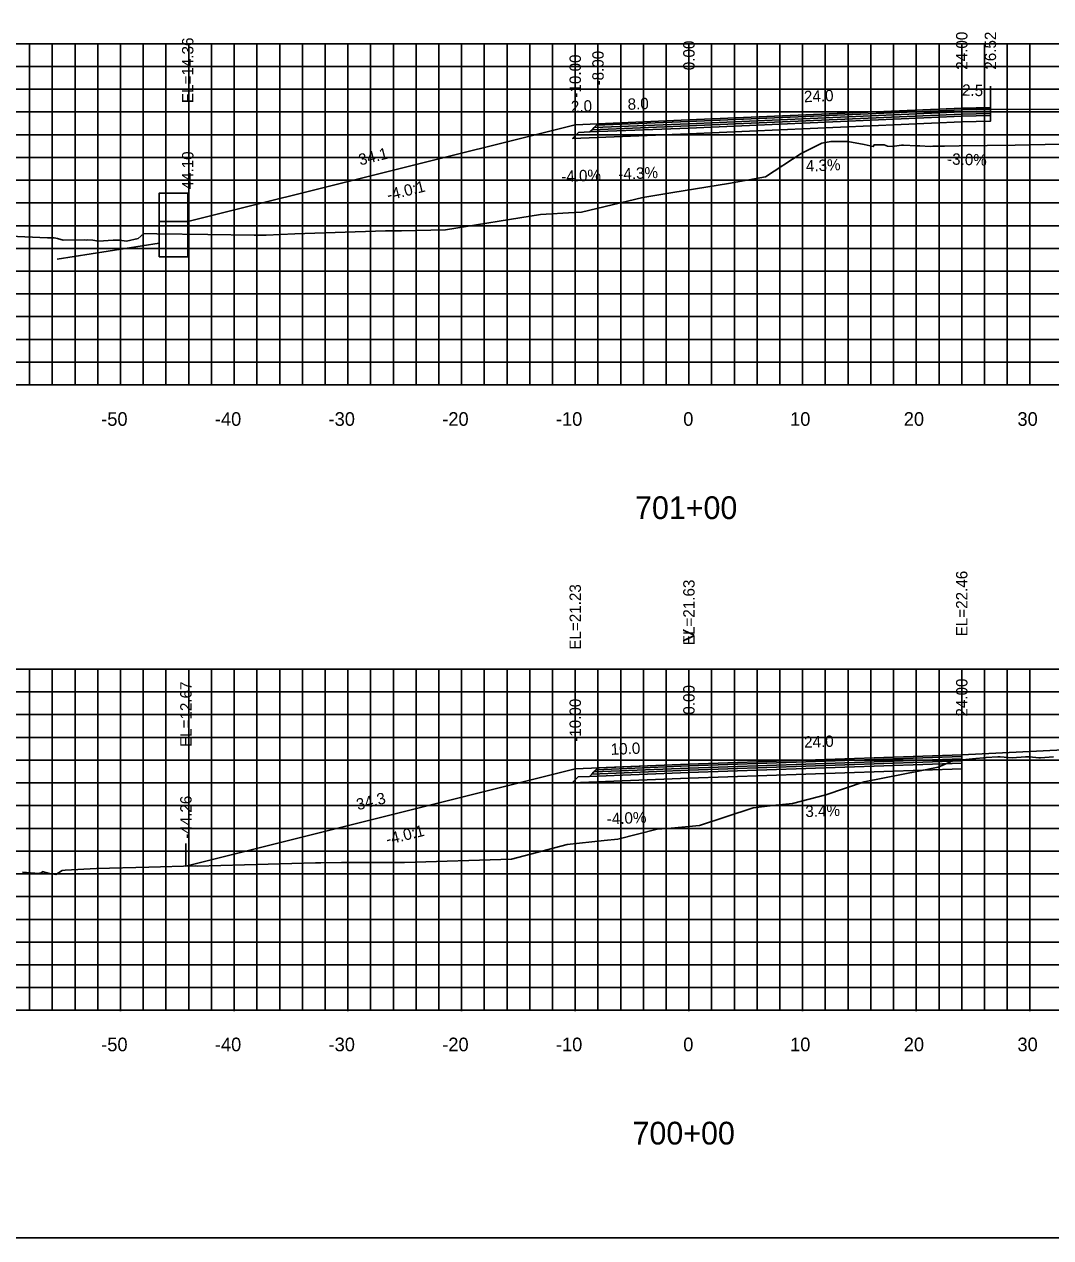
# Model space of a CAD drawing. Extents: x 1797518 to 1804843, y 248068 to 251132.
# Drawn here: x 1802232.5 to 1802322.8, y 250079.4 to 250186.1 of the extents above; entities that cross this region are included whole.
import ezdxf

# ---------------------------------------------------------------- set-up
doc = ezdxf.new("R2010")
doc.units = 0
for name, color, linetype in [('1', 7, 'Continuous'), ('10', 7, 'Continuous'), ('3', 7, 'Continuous'), ('4', 7, 'Continuous'), ('60', 7, 'Continuous'), ('BASE', 7, 'Continuous'), ('CL-CNST', 7, 'Continuous'), ('Level 62', 7, 'Continuous'), ('LOWER BINDER', 7, 'Continuous'), ('M-ROADS', 7, 'Continuous'), ('UPPER BINDER', 7, 'Continuous'), ('WEARING', 7, 'Continuous')]:
    doc.layers.add(name, color=color, linetype=linetype)

msp = doc.modelspace()

# ---------------------------------------------------------------- linework, layer by layer
for p, q in [((1802315, 250178.77), (1802315, 250180.77)), ((1802317.52, 250178.7), (1802317.52, 250180.7)), ((1802281, 250177.31), (1802281, 250179.31)), ((1802283, 250177.39), (1802283, 250179.39)), ((1802291, 250177.74), (1802291, 250179.74)), ((1802246.91, 250168.79), (1802246.91, 250170.79)), ((1802315, 250121.89), (1802315, 250123.89)), ((1802281, 250120.67), (1802281, 250122.67)), ((1802291, 250121.07), (1802291, 250123.07)), ((1802246.75, 250112.1), (1802246.75, 250114.1))]:
    msp.add_line(p, q)
msp.add_lwpolyline([(1802141, 250079.43), (1802441, 250079.43), (1802441, 250269.43), (1802141, 250269.43)], close=True)
at = {"layer": '3'}
msp.add_line((1802235.44, 250165.5), (1802244.4, 250166.88), dxfattribs=at)
at = {"layer": '60'}
for p, q in [((1802141, 250154.43), (1802441, 250154.43)), ((1802241, 250154.37), (1802241, 250154.43)), ((1802251, 250154.37), (1802251, 250154.43)), ((1802261, 250154.37), (1802261, 250154.43)), ((1802271, 250154.37), (1802271, 250154.43)), ((1802281, 250154.37), (1802281, 250154.43)), ((1802291, 250154.37), (1802291, 250154.43)), ((1802301, 250154.37), (1802301, 250154.43)), ((1802311, 250154.37), (1802311, 250154.43)), ((1802321, 250154.37), (1802321, 250154.43)), ((1802141, 250099.43), (1802441, 250099.43)), ((1802241, 250099.37), (1802241, 250099.43)), ((1802251, 250099.37), (1802251, 250099.43)), ((1802261, 250099.37), (1802261, 250099.43)), ((1802271, 250099.37), (1802271, 250099.43)), ((1802281, 250099.37), (1802281, 250099.43)), ((1802291, 250099.37), (1802291, 250099.43)), ((1802301, 250099.37), (1802301, 250099.43)), ((1802311, 250099.37), (1802311, 250099.43)), ((1802321, 250099.37), (1802321, 250099.43))]:
    msp.add_line(p, q, dxfattribs=at)
at = {"layer": 'BASE'}
for points in [[(1802281.28, 250176.63), (1802282.28, 250176.67), (1802291, 250177.02), (1802315, 250178.05), (1802317.52, 250178.11), (1802317.52, 250177.61), (1802315, 250177.55), (1802291, 250176.52), (1802280.76, 250176.11)], [(1802281.25, 250119.96), (1802282.25, 250120), (1802291, 250120.35), (1802315, 250121.17), (1802315, 250121.17), (1802315, 250120.67), (1802315, 250120.67), (1802291, 250119.85), (1802280.73, 250119.44)]]:
    msp.add_lwpolyline(points, close=True, dxfattribs=at)
at = {"layer": 'CL-CNST'}
for points in [[(1802246.91, 250168.79), (1802281, 250177.31), (1802283, 250177.39), (1802291, 250177.74), (1802315, 250178.77), (1802317.52, 250178.7)], [(1802317.54, 250178.67), (1802329.54, 250178.65)], [(1802315, 250121.89), (1802323.96, 250122.34)], [(1802246.75, 250112.1), (1802281, 250120.67), (1802291, 250121.07), (1802315, 250121.89)]]:
    msp.add_lwpolyline(points, dxfattribs=at)
for points in [[(1802246.91, 250168.79), (1802244.41, 250168.79), (1802244.41, 250171.29), (1802246.91, 250171.29)], [(1802244.4, 250165.68), (1802246.91, 250165.68), (1802246.91, 250168.79), (1802244.4, 250168.79)]]:
    msp.add_lwpolyline(points, close=True, dxfattribs=at)
at = {"layer": 'Level 62'}
for p, q in [((1802141, 250184.43), (1802441, 250184.43)), ((1802233, 250154.43), (1802233, 250184.43)), ((1802235, 250154.43), (1802235, 250184.43)), ((1802237, 250154.43), (1802237, 250184.43)), ((1802239, 250154.43), (1802239, 250184.43)), ((1802241, 250154.43), (1802241, 250184.43)), ((1802243, 250154.43), (1802243, 250184.43)), ((1802245, 250154.43), (1802245, 250184.43)), ((1802247, 250154.43), (1802247, 250184.43)), ((1802249, 250154.43), (1802249, 250184.43)), ((1802251, 250154.43), (1802251, 250184.43)), ((1802253, 250154.43), (1802253, 250184.43)), ((1802255, 250154.43), (1802255, 250184.43)), ((1802257, 250154.43), (1802257, 250184.43)), ((1802259, 250154.43), (1802259, 250184.43)), ((1802261, 250154.43), (1802261, 250184.43)), ((1802263, 250154.43), (1802263, 250184.43)), ((1802265, 250154.43), (1802265, 250184.43)), ((1802267, 250154.43), (1802267, 250184.43)), ((1802269, 250154.43), (1802269, 250184.43)), ((1802271, 250154.43), (1802271, 250184.43)), ((1802273, 250154.43), (1802273, 250184.43)), ((1802275, 250154.43), (1802275, 250184.43)), ((1802277, 250154.43), (1802277, 250184.43)), ((1802279, 250154.43), (1802279, 250184.43)), ((1802281, 250154.43), (1802281, 250184.43)), ((1802283, 250154.43), (1802283, 250184.43)), ((1802285, 250154.43), (1802285, 250184.43)), ((1802287, 250154.43), (1802287, 250184.43)), ((1802289, 250154.43), (1802289, 250184.43)), ((1802291, 250154.43), (1802291, 250184.43)), ((1802293, 250154.43), (1802293, 250184.43)), ((1802295, 250154.43), (1802295, 250184.43)), ((1802297, 250154.43), (1802297, 250184.43)), ((1802299, 250154.43), (1802299, 250184.43)), ((1802301, 250154.43), (1802301, 250184.43)), ((1802303, 250154.43), (1802303, 250184.43)), ((1802305, 250154.43), (1802305, 250184.43)), ((1802307, 250154.43), (1802307, 250184.43)), ((1802309, 250154.43), (1802309, 250184.43)), ((1802311, 250154.43), (1802311, 250184.43)), ((1802313, 250154.43), (1802313, 250184.43)), ((1802315, 250154.43), (1802315, 250184.43)), ((1802317, 250154.43), (1802317, 250184.43)), ((1802319, 250154.43), (1802319, 250184.43)), ((1802321, 250154.43), (1802321, 250184.43)), ((1802141, 250182.43), (1802441, 250182.43)), ((1802141, 250180.43), (1802441, 250180.43)), ((1802141, 250178.43), (1802441, 250178.43)), ((1802141, 250176.43), (1802441, 250176.43)), ((1802141, 250174.43), (1802441, 250174.43)), ((1802141, 250172.43), (1802441, 250172.43)), ((1802141, 250170.43), (1802441, 250170.43)), ((1802141, 250168.43), (1802441, 250168.43)), ((1802141, 250166.43), (1802441, 250166.43)), ((1802141, 250164.43), (1802441, 250164.43)), ((1802141, 250162.43), (1802441, 250162.43)), ((1802141, 250160.43), (1802441, 250160.43)), ((1802141, 250158.43), (1802441, 250158.43)), ((1802141, 250156.43), (1802441, 250156.43)), ((1802141, 250154.43), (1802441, 250154.43)), ((1802141, 250129.43), (1802441, 250129.43)), ((1802233, 250099.43), (1802233, 250129.43)), ((1802235, 250099.43), (1802235, 250129.43)), ((1802237, 250099.43), (1802237, 250129.43)), ((1802239, 250099.43), (1802239, 250129.43)), ((1802241, 250099.43), (1802241, 250129.43)), ((1802243, 250099.43), (1802243, 250129.43)), ((1802245, 250099.43), (1802245, 250129.43)), ((1802247, 250099.43), (1802247, 250129.43)), ((1802249, 250099.43), (1802249, 250129.43)), ((1802251, 250099.43), (1802251, 250129.43)), ((1802253, 250099.43), (1802253, 250129.43)), ((1802255, 250099.43), (1802255, 250129.43)), ((1802257, 250099.43), (1802257, 250129.43)), ((1802259, 250099.43), (1802259, 250129.43)), ((1802261, 250099.43), (1802261, 250129.43)), ((1802263, 250099.43), (1802263, 250129.43)), ((1802265, 250099.43), (1802265, 250129.43)), ((1802267, 250099.43), (1802267, 250129.43)), ((1802269, 250099.43), (1802269, 250129.43)), ((1802271, 250099.43), (1802271, 250129.43)), ((1802273, 250099.43), (1802273, 250129.43)), ((1802275, 250099.43), (1802275, 250129.43)), ((1802277, 250099.43), (1802277, 250129.43)), ((1802279, 250099.43), (1802279, 250129.43)), ((1802281, 250099.43), (1802281, 250129.43)), ((1802283, 250099.43), (1802283, 250129.43)), ((1802285, 250099.43), (1802285, 250129.43)), ((1802287, 250099.43), (1802287, 250129.43)), ((1802289, 250099.43), (1802289, 250129.43)), ((1802291, 250099.43), (1802291, 250129.43)), ((1802293, 250099.43), (1802293, 250129.43)), ((1802295, 250099.43), (1802295, 250129.43)), ((1802297, 250099.43), (1802297, 250129.43)), ((1802299, 250099.43), (1802299, 250129.43)), ((1802301, 250099.43), (1802301, 250129.43)), ((1802303, 250099.43), (1802303, 250129.43)), ((1802305, 250099.43), (1802305, 250129.43)), ((1802307, 250099.43), (1802307, 250129.43)), ((1802309, 250099.43), (1802309, 250129.43)), ((1802311, 250099.43), (1802311, 250129.43)), ((1802313, 250099.43), (1802313, 250129.43)), ((1802315, 250099.43), (1802315, 250129.43)), ((1802317, 250099.43), (1802317, 250129.43)), ((1802319, 250099.43), (1802319, 250129.43)), ((1802321, 250099.43), (1802321, 250129.43)), ((1802141, 250127.43), (1802441, 250127.43)), ((1802141, 250125.43), (1802441, 250125.43)), ((1802141, 250123.43), (1802441, 250123.43)), ((1802141, 250121.43), (1802441, 250121.43)), ((1802141, 250119.43), (1802441, 250119.43)), ((1802141, 250117.43), (1802441, 250117.43)), ((1802141, 250115.43), (1802441, 250115.43)), ((1802141, 250113.43), (1802441, 250113.43)), ((1802141, 250111.43), (1802441, 250111.43)), ((1802141, 250109.43), (1802441, 250109.43)), ((1802141, 250107.43), (1802441, 250107.43)), ((1802141, 250105.43), (1802441, 250105.43)), ((1802141, 250103.43), (1802441, 250103.43)), ((1802141, 250101.43), (1802441, 250101.43)), ((1802141, 250099.43), (1802441, 250099.43))]:
    msp.add_line(p, q, dxfattribs=at)
at = {"layer": 'LOWER BINDER'}
for points in [[(1802291, 250177.21), (1802315, 250178.24), (1802317.52, 250178.3), (1802317.52, 250178.11), (1802315, 250178.05), (1802291, 250177.02), (1802282.28, 250176.67), (1802282.48, 250176.87)], [(1802291, 250177.4), (1802315, 250178.43), (1802317.52, 250178.49), (1802317.52, 250178.3), (1802315, 250178.24), (1802291, 250177.21), (1802282.48, 250176.87), (1802282.67, 250177.06)], [(1802291, 250120.54), (1802315, 250121.36), (1802315, 250121.36), (1802315, 250121.17), (1802315, 250121.17), (1802291, 250120.35), (1802282.25, 250120), (1802282.45, 250120.19)], [(1802291, 250120.73), (1802315, 250121.55), (1802315, 250121.56), (1802315, 250121.36), (1802315, 250121.36), (1802291, 250120.54), (1802282.45, 250120.19), (1802282.65, 250120.39)]]:
    msp.add_lwpolyline(points, close=True, dxfattribs=at)
at = {"layer": 'M-ROADS'}
for points in [[(1802231.25, 250167.52), (1802234.58, 250167.36), (1802235.17, 250167.36), (1802235.45, 250167.3), (1802235.94, 250167.17), (1802237.86, 250167.18), (1802238, 250167.17), (1802238.11, 250167.18), (1802238.55, 250167.17), (1802239.07, 250167.08), (1802240.34, 250167.17), (1802240.91, 250167.17), (1802241.53, 250167.07), (1802242.55, 250167.29), (1802243.06, 250167.73), (1802244.18, 250167.71), (1802248.69, 250167.65), (1802252.75, 250167.59), (1802253.3, 250167.59), (1802253.8, 250167.59), (1802256.32, 250167.71), (1802264.3, 250167.98), (1802265.72, 250167.97), (1802269.58, 250168.07), (1802277.94, 250169.42), (1802280.92, 250169.59), (1802281.55, 250169.62), (1802286.94, 250170.9), (1802289.58, 250171.34), (1802294.49, 250172.15), (1802297.73, 250172.72), (1802300.88, 250174.77), (1802302.68, 250175.7), (1802303.49, 250175.83), (1802304.97, 250175.83), (1802306.43, 250175.56), (1802307.22, 250175.39), (1802307.31, 250175.55), (1802308.18, 250175.55), (1802308.48, 250175.41), (1802308.89, 250175.39), (1802309.69, 250175.5), (1802309.77, 250175.5), (1802309.88, 250175.5), (1802311.02, 250175.45), (1802311.31, 250175.45), (1802312.23, 250175.4), (1802312.45, 250175.41), (1802313.49, 250175.42), (1802314.78, 250175.44), (1802319.71, 250175.52), (1802323.66, 250175.59)], [(1802232.38, 250111.57), (1802233.82, 250111.47), (1802234.1, 250111.54), (1802234.12, 250111.63), (1802234.74, 250111.46), (1802235.3, 250111.38), (1802235.86, 250111.73), (1802236.13, 250111.76), (1802238.9, 250111.89), (1802243.48, 250112.01), (1802247.56, 250112.13), (1802247.73, 250112.12), (1802258.16, 250112.39), (1802258.61, 250112.4), (1802260.43, 250112.43), (1802261.82, 250112.43), (1802262.96, 250112.43), (1802265.98, 250112.44), (1802275.39, 250112.73), (1802280.29, 250114.02), (1802283.54, 250114.36), (1802284.74, 250114.49), (1802288.22, 250115.36), (1802289.44, 250115.46), (1802291.94, 250115.67), (1802296.65, 250117.24), (1802298.65, 250117.47), (1802300.1, 250117.63), (1802303.04, 250118.39), (1802306.41, 250119.53), (1802311.35, 250120.5), (1802312.92, 250120.81), (1802314.22, 250121.38), (1802316.24, 250121.57), (1802316.91, 250121.63), (1802317.15, 250121.65), (1802318.17, 250121.73), (1802318.37, 250121.73), (1802318.74, 250121.68), (1802319.45, 250121.63), (1802320.62, 250121.73), (1802320.69, 250121.73), (1802320.95, 250121.71), (1802321.78, 250121.64), (1802321.89, 250121.64), (1802321.94, 250121.63), (1802323.07, 250121.72)]]:
    msp.add_lwpolyline(points, dxfattribs=at)
at = {"layer": 'UPPER BINDER'}
for points in [[(1802317.52, 250178.49), (1802317.52, 250178.68), (1802315, 250178.62), (1802291, 250177.59), (1802282.87, 250177.26), (1802282.67, 250177.06), (1802291, 250177.4), (1802315, 250178.43)], [(1802315, 250121.56), (1802315, 250121.74), (1802315, 250121.74), (1802291, 250120.92), (1802282.85, 250120.59), (1802282.65, 250120.39), (1802291, 250120.73), (1802315, 250121.55)]]:
    msp.add_lwpolyline(points, close=True, dxfattribs=at)
at = {"layer": 'WEARING'}
for points in [[(1802317.52, 250178.68), (1802317.52, 250178.83), (1802315, 250178.77), (1802291, 250177.74), (1802283, 250177.39), (1802282.87, 250177.26), (1802291, 250177.59), (1802315, 250178.62)], [(1802315, 250121.74), (1802315, 250121.89), (1802315, 250121.89), (1802291, 250121.07), (1802283, 250120.75), (1802282.85, 250120.59), (1802291, 250120.92), (1802315, 250121.74)]]:
    msp.add_lwpolyline(points, close=True, dxfattribs=at)

# ---------------------------------------------------------------- texts
for p in [(1802264.56, 250170.62), (1802264.48, 250113.96)]:
    msp.add_text('-4.0:1', height=1, rotation=14.0362).set_placement(p)
at = {"layer": '1'}
for s, p in [('701+00', (1802286.26, 250142.63)), ('700+00', (1802286.04, 250087.63))]:
    msp.add_text(s, height=2, dxfattribs=at).set_placement(p)
at = {"layer": '10'}
for s, p in [('-50', (1802239.3, 250150.83)), ('-40', (1802249.3, 250150.83)), ('-30', (1802259.3, 250150.83)), ('-20', (1802269.3, 250150.83)), ('-10', (1802279.3, 250150.83)), ('0', (1802290.5, 250150.83)), ('10', (1802299.9, 250150.83)), ('20', (1802309.9, 250150.83)), ('30', (1802319.9, 250150.83)), ('-50', (1802239.3, 250095.83)), ('-40', (1802249.3, 250095.83)), ('-30', (1802259.3, 250095.83)), ('-20', (1802269.3, 250095.83)), ('-10', (1802279.3, 250095.83)), ('0', (1802290.5, 250095.83)), ('10', (1802299.9, 250095.83)), ('20', (1802309.9, 250095.83)), ('30', (1802319.9, 250095.83))]:
    msp.add_text(s, height=1.2, dxfattribs=at).set_placement(p)
at = {"layer": '3'}
for s, p in [('24.00', (1802315.5, 250182.14)), ('26.52', (1802318.02, 250182.15)), ('EL=14.36', (1802247.41, 250179.21)), ('0.00', (1802291.5, 250182.1)), ('-10.00', (1802281.5, 250179.69)), ('-8.00', (1802283.5, 250180.76)), ('-44.10', (1802247.41, 250171.17)), ('EL=21.63', (1802291.5, 250131.54)), ('EL=22.46', (1802315.5, 250132.32)), ('EL=21.23', (1802281.5, 250131.14)), ('EL=12.67', (1802247.25, 250122.58)), ('0.00', (1802291.5, 250125.43)), ('24.00', (1802315.5, 250125.26)), ('-10.00', (1802281.5, 250123.04)), ('-44.26', (1802247.25, 250114.51))]:
    msp.add_text(s, height=1, rotation=90, dxfattribs=at).set_placement(p)
at = {"layer": '4'}
for s, rotation, p in [('24.0', 2.4736, (1802301.14, 250179.28)), ('2.5', 358.2621, (1802315.01, 250179.87)), ('2.0', 2.2906, (1802280.64, 250178.4)), ('8.0', 2.4736, (1802285.63, 250178.61)), ('34.1', 14.0362, (1802262.08, 250173.72)), ('-3.0%', 358.2621, (1802313.7, 250173.81)), ('-4.3%', 2.4736, (1802284.81, 250172.47)), ('4.3%', 2.4736, (1802301.31, 250173.18)), ('-4.0%', 2.2906, (1802279.79, 250172.26)), ('24.0', 1.9759, (1802301.15, 250122.52)), ('10.0', 2.2906, (1802284.14, 250121.89)), ('34.3', 14.0362, (1802261.88, 250117.02)), ('-4.0%', 2.2906, (1802283.79, 250115.77)), ('3.4%', 1.9759, (1802301.26, 250116.42))]:
    msp.add_text(s, height=1, rotation=rotation, dxfattribs=at).set_placement(p)
at = {"layer": '60'}
msp.add_text('>', height=1.5, dxfattribs=at).set_placement((1802290.39, 250131.68))

doc.saveas('drawing.dxf')
